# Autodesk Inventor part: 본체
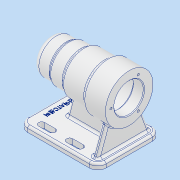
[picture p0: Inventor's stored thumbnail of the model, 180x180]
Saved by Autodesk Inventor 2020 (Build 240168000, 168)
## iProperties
Created: 2021-10
Part Number: 본체
Material: 알루미늄 6061
Document SubType Name: Modeling
Designer: user
Density: 2.7 g/cm^3
Appearance: 알루미늄 - 평지
Mass: 693.151 g
Surface Area: 698.728 cm^2
Volume: 256.723 cm^3
Author: user
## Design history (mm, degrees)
sketch "스케치1"
  geometry: L1 (0, 0)-(-112, 0); L2 (-112, 0)-(-112, 25); L3 (-112, 25)-(-88, 25); L4 (-88, 25)-(-88, 27); L5 (-88, 27)-(-66, 27); L6 (-66, 27)-(-66, 30); L7 (-66, 30)-(-32, 30); L8 (-32, 30)-(-32, 34); L9 (-32, 34)-(0, 34); L10 (0, 34)-(0, 21); L11 (0, 21)-(-15, 21); L12 (-15, 21)-(-15, 21); L13 (-18, 24)-(-66, 24); L14 (-69, 21)-(-69, 21); L15 (-69, 21)-(-80.7, 21); L16 (-81, 20.7)-(-81, 17.5); L17 (-81, 17.5)-(-98.7, 17.5); L18 (-99, 17.2)-(-99, 16); L19 (-99, 16)-(-102.7, 16); L20 (-103, 15.7)-(-103, 10.5); L21 (-103, 10.5)-(-103, 10.5); L22 (-106, 7.5)-(-106, 0); L23 (-112, 0)-(-106, 0); A1 r 3 centre (-103, 7.5) between (-103, 10.5) and (-106, 7.5); A2 r 0.3 centre (-102.7, 15.7) between (-102.7, 16) and (-103, 15.7); A3 r 0.3 centre (-98.7, 17.2) between (-98.7, 17.5) and (-99, 17.2); A4 r 0.3 centre (-80.7, 20.7) between (-80.7, 21) and (-81, 20.7); A5 r 3 centre (-66, 21) between (-66, 24) and (-69, 21); A6 r 3 centre (-18, 21) between (-15, 21) and (-18, 24); 3 further points
  constraints: 46 end point, 18 perpendicular, 12 point on circle, 12 tangent, 6 centre point, 3 equal radius, 3 vertical, 1 collinear, 1 horizontal
  dimensions: "d0" = 112 distance of L1.start L1.end; "d1" = 34 distance between parallel lines of L1 L9; "d2" = 30 distance between parallel lines of L1 L7; "d3" = 27 distance between parallel lines of L1 L5; "d4" = 25 distance between parallel lines of L1 L3; "d5" = 24 horizontal distance of L2.end L4.end; "d6" = 46 horizontal distance of L6.end L2.end; "d7" = 80 horizontal distance of L8.end L2.end; "d8" = 112 horizontal distance of L9.end L2.end; "d9" = 15 distance between parallel lines of L10 L12; "d10" = 21 distance between parallel lines of L1 L11; "d11" = 54 distance between parallel lines of L12 L14; "d12" = 24 distance between parallel lines of L1 L13; "d14" = 12 distance between parallel lines of L14 L16; "d15" = 21 distance between parallel lines of L1 L15; "d16" = 18 distance between parallel lines of L16 L18; "d17" = 17.5 distance between parallel lines of L1 L17; "d19" = 4 distance between parallel lines of L18 L20; "d20" = 3 distance between parallel lines of L20 L22; "d21" = 16 distance between parallel lines of L1 L19; "d22" = 10.5 distance between parallel lines of L1 L21; "d23" = 3 radius of A1; "d24" = 0.3 radius of A2; "d25" = 3 radius of A5
revolve "회전1" sketch "스케치1" stored, may be unused: angle "d26" = 90 deg
chamfer "모따기1" distance "d27" = 1; stored, may be unused: second distance "d28" = 2, angle "d29" = 45 deg
node "작업 평면1"
sketch "스케치2"
  geometry: L1 (0, -45)-(112, -45); L2 (112, -45)-(112, 45); L3 (112, 45)-(0, 45); L4 (0, 45)-(0, -45); 2 further points
  constraints: 8 end point, 2 parallel, 1 coincident, 1 horizontal, 1 midpoint, 1 perpendicular
  dimensions: "d31" = 112 distance between parallel lines of L4 L2; "d32" = 90 distance between parallel lines of L3 L1
extrude "돌출1" join sketch "스케치2" distance "d33" = 8; taper "d34" = 0 deg
sketch "스케치3"
  geometry: 2 further points
  constraints: 1 horizontal alignment
  dimensions: "d35" = 26 distance of point (0, 0) point (-26, 0)
hole "구멍1" sketch "스케치3" at (-26, 0) diameter "d36" = 3.242; stored, may be unused: countersink angle "d40" = 90 deg, drill point angle "d42" = 118 deg; dims "d37" = 8, "d38" = 4, "d39" = 2, "d41" = 11
sketch "스케치6"
  geometry: L1 (-85, -4)-(-8, -4); L2 (-8, -4)-(-8, 4); L3 (-8, 4)-(-85, 4); L4 (-85, 4)-(-85, -4); L5 (0, -45)-(0, 45) reference; 3 further points
  constraints: 8 end point, 2 midpoint, 2 parallel, 1 horizontal, 1 horizontal alignment, 1 perpendicular
  dimensions: "d50" = 8 distance between parallel lines of L1 L3; "d52" = 8 distance between parallel lines of L5 L2; "d97" = 77 distance from line of L1.end L4
extrude "돌출2" join sketch "스케치6" stored distance "d54" = 8; taper "d55" = 0 deg
node "작업 평면3"
sketch "스케치7"
  geometry: L1 (-23.409, -24.658)-(-37, -62); L2 (45, -62)-(-45, -62) reference; L3 (-45, -70)-(-45, -62) reference; A1 r 34 centre (0, 0) between (4, -33.764) and (-4, -33.764) reference; 1 further point
  constraints: 2 end point, 1 point on circle, 1 point on line
  dimensions: "d58" = 110 deg angle of L2 L1; "d60" = 8 distance from line of L3 L1.end
feature "리브1" sketch "스케치7" dims "d61" = 1, "d62" = 8, "d63" = 0, "d64" = 0, "d65" = 1, "d66" = 1
feature "면 기울기1" dims angle "d68" = 15 deg
fillet "모깎기1" dims "d69" = 8
fillet "모깎기2" dims "d70" = 3
sketch "스케치10"
  geometry: L1 (-92, -33)-(-77, -33); L2 (-92, -37.5)-(-77, -37.5); L3 (-77, -28.5)-(-92, -28.5); L4 (-52, -33)-(-37, -33); L5 (-52, -37.5)-(-37, -37.5); L6 (-37, -28.5)-(-52, -28.5); L7 (-92, 33)-(-77, 33); L8 (-92, 28.5)-(-77, 28.5); L9 (-77, 37.5)-(-92, 37.5); L10 (-52, 33)-(-37, 33); L11 (-52, 28.5)-(-37, 28.5); L12 (-37, 37.5)-(-52, 37.5); L13 (-112, 45)-(-112, -45) reference; L14 (-112, -45)-(0, -45) reference; A1 r 4.5 centre (-92, -33) between (-92, -28.5) and (-92, -37.5); A2 r 4.5 centre (-77, -33) between (-77, -37.5) and (-77, -28.5); A3 r 4.5 centre (-52, -33) between (-52, -28.5) and (-52, -37.5); A4 r 4.5 centre (-37, -33) between (-37, -37.5) and (-37, -28.5); A5 r 4.5 centre (-92, 33) between (-92, 37.5) and (-92, 28.5); A6 r 4.5 centre (-77, 33) between (-77, 28.5) and (-77, 37.5); A7 r 4.5 centre (-52, 33) between (-52, 37.5) and (-52, 28.5); A8 r 4.5 centre (-37, 33) between (-37, 28.5) and (-37, 37.5); 5 further points
  constraints: 32 end point, 16 point on circle, 16 tangent, 8 centre point, 5 parallel, 4 midpoint, 4 point on line, 1 horizontal
  dimensions: "d71" = 9 diameter of A2; "d72" = 15 distance of L4.start L4.end; "d73" = 9 diameter of A4; "d74" = 15 distance of L7.start L7.end; "d75" = 9 diameter of A6; "d76" = 15 distance of L10.start L10.end; "d77" = 9 diameter of A8; "d78" = 15 distance of L1.start L1.end; "d79" = 20 distance from line of L13 L1.start; "d80" = 25 distance of L4.start L1.end; "d81" = 20 distance from line of L13 L7.start; "d82" = 25 distance of L10.start L7.end; "d84" = 33 vertical distance of point (0, 0) point (-84.5, -33); "d85" = 33 vertical distance of L7.start point (0, 0)
extrude "돌출3" cut sketch "스케치10" distance "d86" = 8; taper "d87" = 0 deg
fillet "모깎기3" dims "d88" = 12
fillet "모깎기4" dims "d89" = 3
fillet "모깎기5" dims "d90" = 3
fillet "모깎기6" dims "d91" = 3
sketch "스케치11"
  geometry: L1 (-112, 33)-(-112, -33) reference; 2 further points
  constraints: 1 horizontal alignment, 1 other
  dimensions: "d94" = 12 distance from line of L1 point (-100, 0)
feature "엠보싱1" sketch "스케치11" dims "d0" = 112, "d1" = 34, "d2" = 30, "d3" = 27, "d4" = 25, "d5" = 24, "d6" = 46, "d7" = 80, "d8" = 112, "d9" = 15, "d10" = 21, "d11" = 54, "d12" = 24, "d14" = 12, "d15" = 21, "d16" = 18, "d17" = 17.5, "d19" = 4, "d20" = 3, "d21" = 16, "d22" = 10.5, "d23" = 3, "d24" = 0.3, "d25" = 3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
fillet "모깎기7" dims "d95" = 3
fillet "모깎기8" dims "d96" = 3
node "솔리드1"
pattern_circular "원형 패턴1" dims angle "d44" = 360 deg
mirror "미러1"
feature "A9D066F2-1C7D-4E18-AEED-F7BC21143FA4" dims "d36" = 3.242, "d37" = 8, "d38" = 4, "d39" = 2, "d40" = 90 deg, "d41" = 11, "d42" = 118 deg
other parameters: "d57" = -8
